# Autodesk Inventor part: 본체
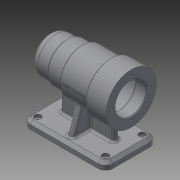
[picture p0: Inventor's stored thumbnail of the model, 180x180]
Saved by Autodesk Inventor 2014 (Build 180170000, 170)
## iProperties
Created: 2016-06
Part Number: 본체
Material: 일반
Document SubType Name: Modeling
Designer: 601-
Density: 1 g/cm^3
Appearance: 기본값
Author: 601-
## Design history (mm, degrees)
sketch "Sketch1"
  geometry: L1 (0, 0)-(0, 25); L2 (0, 25)-(25, 25); L3 (25, 25)-(25, 27); L4 (25, 27)-(45, 27); L5 (45, 27)-(45, 30); L6 (45, 30)-(84, 30); L7 (84, 30)-(84, 34); L8 (84, 34)-(112, 34); L9 (112, 34)-(112, 0); L10 (112, 0)-(0, 0)
  constraints: 20 end point, 6 parallel, 3 perpendicular, 1 vertical
  dimensions: "d0" = 25 distance between parallel lines of L3 L1; "d1" = 45 distance between parallel lines of L5 L1; "d2" = 84 distance between parallel lines of L7 L1; "d3" = 112 distance between parallel lines of L9 L1; "d4" = 68 diameter of L8 L10; "d5" = 60 diameter of L6 L10; "d6" = 54 diameter of L4 L10; "d7" = 50 diameter of L2 L10
revolve "Revolution1" sketch "Sketch1" stored, may be unused: angle "d8" = 90 deg
workplane "Work Plane1"
sketch "Sketch2"
  geometry: L1 (0, 35)-(112, 35); L2 (112, 35)-(112, -35); L3 (112, -35)-(0, -35); L4 (0, -35)-(0, 35); 2 further points
  constraints: 8 end point, 2 parallel, 1 coincident, 1 horizontal, 1 midpoint, 1 perpendicular
  dimensions: "d10" = 112 distance of L1.start L1.end; "d11" = 70 distance of L3.end L1.start
extrude "Extrusion1" join sketch "Sketch2" distance "d12" = 10; taper "d13" = 0 deg
sketch "Sketch3"
  geometry: L1 (-112, -60)-(0, -60) reference; L2 (-20, -25)-(-20, -60); L3 (0, -70)-(0, -60) reference; L4 (-112, -70)-(-112, -60) reference; L5 (-92, -34)-(-92, -60); L6 (0, -25)-(-25, -25) reference; L7 (-84, -34)-(-112, -34) reference; L8 (-20, -25)-(-44.839, -13.339); L9 (-44.839, -13.339)-(-81.221, -16.559); L10 (-81.221, -16.559)-(-92, -22.193); L11 (-92, -22.193)-(-92, -34); L12 (-92, -60)-(-20, -60); 1 further point
  constraints: 14 end point, 4 point on line, 3 perpendicular, 1 collinear
  dimensions: "d14" = 20 distance between parallel lines of L2 L3; "d15" = 20 distance between parallel lines of L5 L4
extrude "Extrusion2" join sketch "Sketch3" stored distance "d16" = 8; taper "d17" = 0 deg
workplane "Work Plane2"
sketch "Sketch4"
  geometry: L1 (-70, -35)-(-60, -35) reference; L2 (-70, 35)-(-60, 35) reference; L3 (-60, -35)-(-60, 35) reference; L4 (-60, -28)-(-25.68, -15.509); L5 (0, 0)-(-60, 0); L6 (-60, 28)-(-25.68, 15.509); L7 (-60, 28)-(-60, -28); L8 (-25.68, 15.509)-(-25.68, -15.509); A1 r 30 centre (0, 0) between (-29.732, -4) and (-29.732, 4) reference; 1 further point
  constraints: 10 end point, 2 symmetric about line, 1 collinear, 1 midpoint, 1 parallel, 1 point on circle, 1 point on line
  dimensions: "d18" = 7 distance from line of L1 L4.start; "d19" = 110 deg angle of L4 L3
extrude "Extrusion3" join sketch "Sketch4" stored distance "d20" = 8; taper "d21" = 0 deg
fillet "Fillet1" dims "d22" = 10
sketch "Sketch5"
  geometry: L1 (-6, 0)-(-6, 10.5); L2 (-6, 10.5)-(-9, 10.5); L3 (-9, 10.5)-(-9, 16); L4 (-9, 16)-(-13, 16); L5 (-13, 16)-(-13, 17.5); L6 (-13, 17.5)-(-31, 17.5); L7 (-31, 17.5)-(-31, 21); L8 (-31, 21)-(-43, 21); L9 (-43, 21)-(-43, 24); L10 (-43, 24)-(-97, 24); L11 (-97, 24)-(-97, 21); L12 (-112, 34)-(-112, -34) reference; L13 (-97, 21)-(-112, 21); L14 (-112, 21)-(-112, 0); L15 (-112, 0)-(-6, 0); 1 further point
  constraints: 28 end point, 9 parallel, 3 perpendicular, 1 midpoint, 1 point on line, 1 vertical
  dimensions: "d23" = 48 diameter of L10 L15; "d24" = 42 diameter of L13 L15; "d25" = 42 diameter of L8 L15; "d26" = 35 diameter of L6 L15; "d27" = 32 diameter of L4 L15; "d28" = 21 diameter of L2 L15; "d29" = 3 distance between parallel lines of L3 L1; "d30" = 4 distance between parallel lines of L5 L3; "d31" = 18 distance between parallel lines of L7 L5; "d32" = 12 distance between parallel lines of L9 L7; "d33" = 15 distance between parallel lines of L14 L11; "d34" = 54 distance between parallel lines of L11 L9
revolve "Revolution2" sketch "Sketch5" stored, may be unused: angle "d35" = 90 deg
sketch "Sketch6" dims "d36" = 52
  geometry: L1 (0, 0)-(-26, 0); 3 further points
  constraints: 3 coincident, 2 end point, 1 horizontal, 1 horizontal alignment, 2 other
hole "Hole1" sketch "Sketch6" at (-26, 0) diameter "d37" = 3.242; stored, may be unused: countersink angle "d41" = 90 deg, drill point angle "d43" = 118 deg; dims "d38" = 8, "d39" = 4, "d40" = 2, "d42" = 11
pattern_circular "Circular Pattern1" dims angle "d45" = 360 deg
fillet "Fillet2" dims "d47" = 10
sketch "Sketch7"
  geometry: L1 (102, -35)-(10, -35) reference; L2 (0, -25)-(0, 25) reference; L3 (10, 35)-(102, 35) reference; L4 (112, 25)-(112, -25) reference; 5 further points
  dimensions: "d48" = 92 distance of point (102, 25) point (10, 25); "d49" = 50 distance of point (10, -25) point (10, 25); "d50" = 10 distance from line of L1 point (10, -25); "d51" = 10 distance from line of point (10, -25) L2; "d52" = 10 distance from line of L2 point (10, 25); "d53" = 10 distance from line of point (10, 25) L3 (derived); "d54" = 10 distance from line of L3 point (102, 25); "d55" = 10 distance from line of L4 point (102, -25); "d56" = 10 distance from line of L1 point (102, -25)
hole "Hole2" sketch "Sketch7" at (10, 25), (102, 25), (102, -25), (10, -25) diameter "d57" = 5; stored, may be unused: countersink angle "d61" = 90 deg, drill point angle "d63" = 118 deg; dims "d58" = 8, "d59" = 9, "d60" = 4, "d62" = 11
chamfer "Chamfer1" distance "d64" = 4; stored, may be unused: second distance "d65" = 2, angle "d66" = 45 deg
chamfer "Chamfer2" distance "d67" = 1; stored, may be unused: second distance "d68" = 2, angle "d69" = 45 deg
chamfer "Chamfer3" distance "d70" = 1; stored, may be unused: second distance "d71" = 2, angle "d72" = 45 deg
fillet "Fillet3" dims "d73" = 3
fillet "Fillet4" dims "d74" = 0.3
fillet "Fillet5" dims "d75" = 3
fillet "Fillet6" dims "d76" = 3
fillet "Fillet7" dims "d77" = 3
fillet "Fillet8" dims "d78" = 3
fillet "Fillet9" dims "d79" = 3
workplane "Work Plane6"
  workplane "Work Plane5"
sketch "Sketch10"
  geometry: L1 (-16.092, 2.402)-(17.092, 2.402); L2 (17.092, 2.402)-(17.092, -2.402); L3 (17.092, -2.402)-(-16.092, -2.402); L4 (-16.092, -2.402)-(-16.092, 2.402); L5 (-16.092, 0)-(17.092, 0); L6 (0.5, 2.402)-(0.5, -2.402); L7 (-47.5, 34)-(-47.5, -34) reference; 3 further points
  constraints: 6 midpoint, 4 end point, 1 horizontal alignment, 2 other
  dimensions: "d81" = 48 distance from line of L7 point (0.5, 0)
extrude "Extrusion4" join sketch "Sketch10" distance "d82" = 0.5; taper "d83" = 0 deg
body "Solid1"
